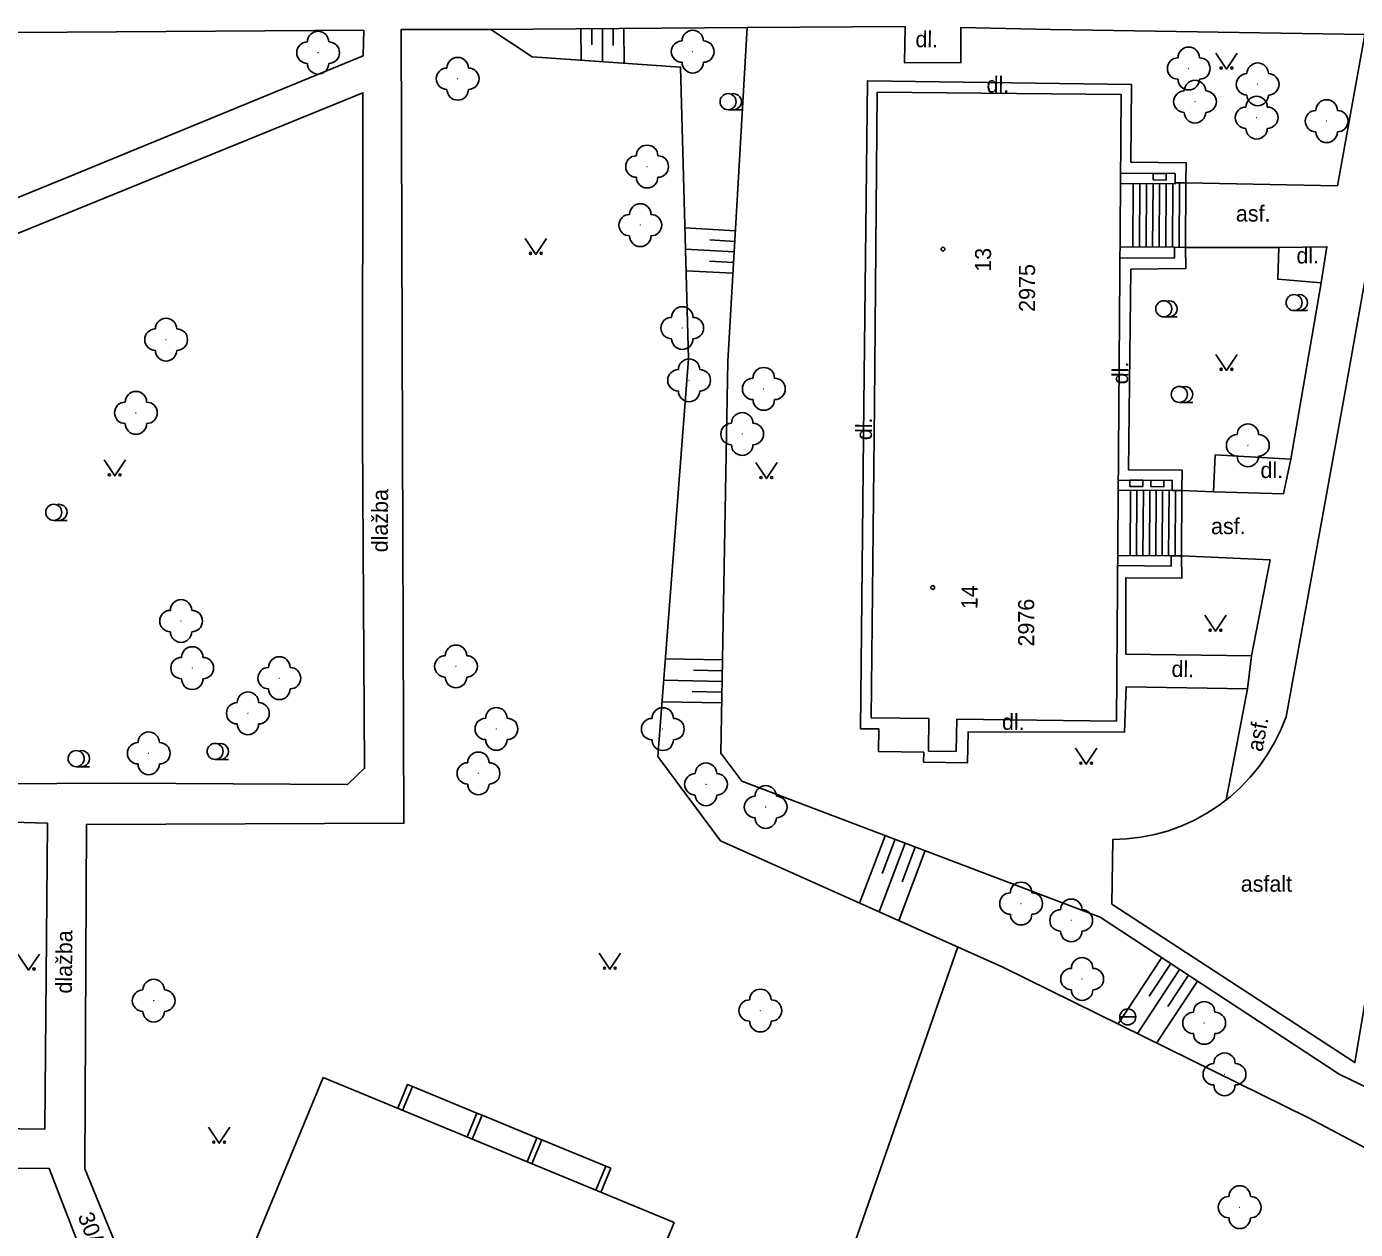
# Model space of a CAD drawing. Extents: x -584400 to -581602, y -1210894 to -1208793.
# Drawn here: x -582480.2 to -582418.1, y -1209940.8 to -1209884.6 of the extents above; entities that cross this region are included whole.
import ezdxf

# ---------------------------------------------------------------- set-up
doc = ezdxf.new("R2010")
doc.units = 0
for name, color, linetype in [('BUDOVY_MĚŘ', 7, 'Continuous'), ('POMOC_POPIS', 7, 'Continuous'), ('ROZHRANÍ_PLOCH', 7, 'Continuous'), ('VÝŠKOPIS', 7, 'Continuous'), ('ZELEŇ', 7, 'Continuous'), ('ZN_BUDOV', 7, 'Continuous'), ('ZN_DOPLŇKOVÉ', 7, 'Continuous'), ('ZN_KULTUR', 7, 'Continuous'), ('Č_POPIS_EVID', 7, 'Continuous')]:
    doc.layers.add(name, color=color, linetype=linetype)

msp = doc.modelspace()

# ---------------------------------------------------------------- linework, layer by layer
at = {"layer": 'BUDOVY_MĚŘ'}
for points in [[(-582440.48, -1209887.69), (-582440.61, -1209902.29)], [(-582429.08, -1209887.81), (-582440.48, -1209887.69)], [(-582429.31, -1209917.09), (-582429.08, -1209887.81)], [(-582427.59, -1209891.49), (-582427.59, -1209891.79)], [(-582426.99, -1209891.5), (-582427.59, -1209891.49)], [(-582426.99, -1209891.5), (-582426.99, -1209891.8)], [(-582426.99, -1209891.8), (-582427.59, -1209891.79)], [(-582440.61, -1209902.29), (-582440.76, -1209916.93)], [(-582428.68, -1209905.83), (-582428.68, -1209906.13)], [(-582428.08, -1209905.83), (-582428.68, -1209905.83)], [(-582428.08, -1209905.83), (-582428.08, -1209906.13)], [(-582427.7, -1209905.83), (-582427.7, -1209906.13)], [(-582427.1, -1209905.84), (-582427.7, -1209905.83)], [(-582427.1, -1209905.84), (-582427.1, -1209906.14)], [(-582428.08, -1209906.13), (-582428.68, -1209906.13)], [(-582427.1, -1209906.14), (-582427.7, -1209906.13)], [(-582440.76, -1209916.93), (-582438.07, -1209916.97)], [(-582438.09, -1209918.49), (-582438.07, -1209916.97)], [(-582436.77, -1209916.99), (-582436.79, -1209918.51)], [(-582436.77, -1209916.99), (-582429.31, -1209917.09)], [(-582436.79, -1209918.51), (-582438.09, -1209918.49)], [(-582466.36, -1209933.74), (-582449.97, -1209940.52), (-582453.87, -1209949.94), (-582470.27, -1209943.18), (-582466.36, -1209933.74)]]:
    msp.add_lwpolyline(points, dxfattribs=at)
at = {"layer": 'ROZHRANÍ_PLOCH'}
for points in [[(-582487.79, -1209884.94), (-582478.32, -1209884.89), (-582464.47, -1209884.8), (-582464.49, -1209885.99), (-582477.95, -1209891.52), (-582496.11, -1209898.92)], [(-582475.85, -1209942.04), (-582477.49, -1209938.01), (-582477.42, -1209921.91), (-582462.59, -1209921.86), (-582462.65, -1209904.04), (-582462.72, -1209884.77), (-582458.53, -1209884.77), (-582446.56, -1209884.67), (-582439.17, -1209884.63), (-582439.21, -1209886.32), (-582436.57, -1209886.31), (-582436.58, -1209884.67), (-582432.38, -1209884.76), (-582417.71, -1209885), (-582418.98, -1209892.07), (-582426.06, -1209891.93), (-582426.05, -1209890.99), (-582428.63, -1209890.97), (-582428.6, -1209887.34), (-582440.94, -1209887.16), (-582441.11, -1209902.31), (-582441.27, -1209917.44), (-582440.41, -1209917.45), (-582440.42, -1209918.51), (-582438.31, -1209918.54), (-582438.32, -1209919), (-582436.26, -1209919.03), (-582436.24, -1209917.59), (-582428.93, -1209917.6), (-582428.86, -1209915.48), (-582423.19, -1209915.58), (-582424.18, -1209920.77)], [(-582415.66, -1209885.04), (-582418.63, -1209901.68), (-582421.38, -1209916.89), (-582421.63, -1209917.5), (-582421.92, -1209918.09), (-582422.26, -1209918.66), (-582422.64, -1209919.2), (-582423.06, -1209919.71), (-582423.51, -1209920.19), (-582424, -1209920.63), (-582424.18, -1209920.77), (-582424.53, -1209921.03), (-582425.08, -1209921.39), (-582425.66, -1209921.71), (-582426.26, -1209921.98), (-582426.88, -1209922.21), (-582427.52, -1209922.38), (-582428.17, -1209922.51), (-582428.82, -1209922.59), (-582429.48, -1209922.62), (-582429.52, -1209925.64), (-582418.17, -1209933.04), (-582417.7, -1209930.28)], [(-582496.62, -1209900.8), (-582477.39, -1209892.97), (-582464.51, -1209887.72), (-582464.52, -1209903.76), (-582464.43, -1209919.29), (-582465.22, -1209920.05), (-582475.91, -1209919.99), (-582484.59, -1209920.04), (-582484.6, -1209914.6), (-582485.27, -1209914.6)], [(-582429.11, -1209891.48), (-582426.57, -1209891.5), (-582426.57, -1209891.98), (-582429.11, -1209891.96)], [(-582428.54, -1209894.93), (-582428.52, -1209891.97)], [(-582428.23, -1209894.93), (-582428.21, -1209891.97)], [(-582427.92, -1209894.93), (-582427.9, -1209891.97)], [(-582427.62, -1209894.93), (-582427.59, -1209891.97)], [(-582427.31, -1209894.93), (-582427.29, -1209891.97)], [(-582427, -1209894.94), (-582426.98, -1209891.98)], [(-582426.69, -1209894.94), (-582426.67, -1209891.98)], [(-582426.6, -1209894.94), (-582426.08, -1209894.95), (-582426.06, -1209891.93), (-582426.57, -1209891.93)], [(-582426.38, -1209894.94), (-582426.36, -1209891.98)], [(-582429.14, -1209894.92), (-582426.6, -1209894.94), (-582426.6, -1209895.45), (-582429.14, -1209895.43)], [(-582424.78, -1209906.37), (-582426.25, -1209906.31), (-582426.24, -1209905.36), (-582428.75, -1209905.34), (-582428.64, -1209895.97), (-582426.07, -1209895.94), (-582426.08, -1209894.95), (-582421.73, -1209894.95), (-582421.77, -1209896.44), (-582419.75, -1209896.61), (-582421.16, -1209904.84), (-582424.69, -1209904.65), (-582424.78, -1209906.37)], [(-582421.73, -1209894.95), (-582419.48, -1209894.92), (-582419.75, -1209896.61)], [(-582424.78, -1209906.37), (-582421.51, -1209906.47), (-582421.16, -1209904.84)], [(-582429.22, -1209905.82), (-582426.7, -1209905.84), (-582426.7, -1209906.31), (-582429.23, -1209906.29)], [(-582428.65, -1209906.3), (-582428.67, -1209909.36)], [(-582428.35, -1209906.3), (-582428.37, -1209909.36)], [(-582428.05, -1209906.3), (-582428.07, -1209909.36)], [(-582427.75, -1209906.3), (-582427.77, -1209909.36)], [(-582427.45, -1209906.3), (-582427.47, -1209909.36)], [(-582427.15, -1209906.31), (-582427.17, -1209909.37)], [(-582426.85, -1209906.31), (-582426.87, -1209909.37)], [(-582426.7, -1209906.31), (-582426.25, -1209906.31), (-582426.27, -1209909.37), (-582426.75, -1209909.37)], [(-582426.55, -1209906.31), (-582426.57, -1209909.37)], [(-582429.25, -1209909.82), (-582426.75, -1209909.84), (-582426.75, -1209909.37), (-582429.25, -1209909.35)], [(-582423, -1209914.04), (-582428.87, -1209913.95), (-582428.87, -1209910.39), (-582426.25, -1209910.4), (-582426.27, -1209909.37), (-582422.13, -1209909.55), (-582423, -1209914.04)], [(-582423, -1209914.04), (-582423.19, -1209915.58)], [(-582479.24, -1209921.86), (-582479.37, -1209936.15), (-582484, -1209936.09), (-582484.04, -1209933.99), (-582480.99, -1209934.06), (-582480.9, -1209921.81), (-582479.24, -1209921.86)], [(-582480.69, -1209957.83), (-582475.89, -1209949.13), (-582475.61, -1209947.19), (-582479.16, -1209938), (-582506.68, -1209937.89), (-582506.72, -1209927.01), (-582507.45, -1209926.2), (-582528.2, -1209925.75), (-582529.35, -1209927.61)], [(-582462.19, -1209934.16), (-582459.18, -1209935.4)], [(-582458.94, -1209935.5), (-582456.38, -1209936.56)], [(-582456.15, -1209936.65), (-582453.16, -1209937.88)]]:
    msp.add_lwpolyline(points, dxfattribs=at)
at = {"layer": 'VÝŠKOPIS'}
for points in [[(-582458.53, -1209884.77), (-582456.6, -1209886.04), (-582449.67, -1209886.53), (-582449.3, -1209900.15), (-582450.73, -1209918.74), (-582447.81, -1209922.68), (-582434.61, -1209928.59), (-582420.34, -1209935.62), (-582401.96, -1209945.35), (-582389.45, -1209947.48)], [(-582454.31, -1209886.2), (-582454.32, -1209884.74)], [(-582453.82, -1209885.48), (-582453.82, -1209884.73)], [(-582453.31, -1209886.27), (-582453.32, -1209884.73)], [(-582452.82, -1209885.51), (-582452.82, -1209884.72)], [(-582452.31, -1209886.34), (-582452.32, -1209884.72)], [(-582391.38, -1209943.01), (-582402.62, -1209941.45), (-582418.91, -1209933.59), (-582430.07, -1209926.24), (-582446.8, -1209919.9), (-582447.79, -1209918.59), (-582447.46, -1209900.26), (-582446.56, -1209884.67)], [(-582449.47, -1209894.03), (-582447.11, -1209894.17)], [(-582448.3, -1209894.6), (-582447.14, -1209894.67)], [(-582449.44, -1209895.03), (-582447.17, -1209895.16)], [(-582449.41, -1209896.04), (-582447.22, -1209896.16)], [(-582448.31, -1209895.6), (-582447.19, -1209895.66)], [(-582450.38, -1209914.18), (-582447.71, -1209914.23)], [(-582450.46, -1209915.18), (-582447.73, -1209915.23)], [(-582449.07, -1209914.7), (-582447.72, -1209914.73)], [(-582449.12, -1209915.7), (-582447.74, -1209915.73)], [(-582450.53, -1209916.18), (-582447.75, -1209916.23)], [(-582441.31, -1209925.59), (-582440.11, -1209922.44)], [(-582440.25, -1209924.2), (-582439.64, -1209922.61)], [(-582440.39, -1209926), (-582439.18, -1209922.79)], [(-582439.48, -1209926.41), (-582438.24, -1209923.14)], [(-582439.32, -1209924.59), (-582438.71, -1209922.97)], [(-582429.23, -1209931.24), (-582427.19, -1209928.14)], [(-582428.33, -1209931.68), (-582426.36, -1209928.69)], [(-582427.78, -1209929.94), (-582426.77, -1209928.41)], [(-582426.91, -1209930.43), (-582425.94, -1209928.96)], [(-582427.43, -1209932.13), (-582425.52, -1209929.24)]]:
    msp.add_lwpolyline(points, dxfattribs=at)
at = {"layer": 'ZELEŇ'}
msp.add_lwpolyline([(-582436.72, -1209927.64), (-582442.95, -1209945.51), (-582431.5, -1209950.17), (-582420.63, -1209954.71), (-582403.11, -1209963.06), (-582400.98, -1209957.39), (-582400.57, -1209953.27)], dxfattribs=at)
for centre in [(-582466.6, -1209885.85), (-582449.1, -1209885.8), (-582425.93, -1209886.59), (-582460.08, -1209887.07), (-582422.71, -1209887.33), (-582425.64, -1209888.14), (-582422.76, -1209888.89), (-582419.49, -1209889.05), (-582451.23, -1209891.17), (-582451.55, -1209893.91), (-582449.59, -1209898.72), (-582473.7, -1209899.26), (-582449.27, -1209901.16), (-582445.78, -1209901.56), (-582475.11, -1209902.68), (-582446.79, -1209903.67), (-582423.17, -1209904.2), (-582473, -1209912.41), (-582472.48, -1209914.61), (-582460.16, -1209914.53), (-582468.41, -1209915.08), (-582469.88, -1209916.72), (-582458.27, -1209917.45), (-582450.5, -1209917.46), (-582474.51, -1209918.59), (-582459.11, -1209919.53), (-582448.48, -1209920.04), (-582445.69, -1209921.1), (-582433.76, -1209925.61), (-582431.42, -1209926.4), (-582430.91, -1209929.14), (-582474.28, -1209930.15), (-582445.94, -1209930.61), (-582425.21, -1209931.19), (-582424.26, -1209933.59), (-582423.55, -1209939.8)]:
    msp.add_circle(centre, 0.0005, dxfattribs=at)
for centre, start, end in [((-582466.6, -1209885.35), 0, 179.99999), ((-582449.1, -1209885.3), 0, 179.99999), ((-582467.1, -1209885.85), 89.99999, 269.99999), ((-582466.1, -1209885.85), 270, 89.99999), ((-582449.6, -1209885.8), 89.99999, 269.99999), ((-582448.6, -1209885.8), 270, 89.99999), ((-582460.08, -1209886.57), 0, 179.99999), ((-582426.43, -1209886.59), 89.99999, 269.99999), ((-582425.93, -1209886.09), 0, 179.99999), ((-582425.43, -1209886.59), 270, 89.99999), ((-582466.6, -1209886.35), 179.99999, 359.99999), ((-582460.58, -1209887.07), 89.99999, 269.99999), ((-582459.58, -1209887.07), 270, 89.99999), ((-582449.1, -1209886.3), 179.99999, 359.99999), ((-582422.71, -1209886.83), 0, 179.99999), ((-582425.93, -1209887.09), 179.99999, 359.99999), ((-582425.64, -1209887.64), 0, 179.99999), ((-582423.21, -1209887.33), 89.99999, 269.99999), ((-582422.21, -1209887.33), 270, 89.99999), ((-582460.08, -1209887.57), 179.99999, 359.99999), ((-582426.14, -1209888.14), 89.99999, 269.99999), ((-582425.14, -1209888.14), 270, 89.99999), ((-582422.76, -1209888.39), 0, 179.99999), ((-582422.71, -1209887.83), 179.99999, 359.99999), ((-582423.26, -1209888.89), 89.99999, 269.99999), ((-582422.26, -1209888.89), 270, 89.99999), ((-582419.99, -1209889.05), 89.99999, 269.99999), ((-582419.49, -1209888.55), 0, 179.99999), ((-582418.99, -1209889.05), 270, 89.99999), ((-582425.64, -1209888.64), 179.99999, 359.99999), ((-582422.76, -1209889.39), 179.99999, 359.99999), ((-582419.49, -1209889.55), 179.99999, 359.99999), ((-582451.23, -1209890.67), 0, 179.99999), ((-582451.73, -1209891.17), 89.99999, 269.99999), ((-582450.73, -1209891.17), 270, 89.99999), ((-582451.23, -1209891.67), 179.99999, 359.99999), ((-582451.55, -1209893.41), 0, 179.99999), ((-582452.05, -1209893.91), 89.99999, 269.99999), ((-582451.05, -1209893.91), 270, 89.99999), ((-582451.55, -1209894.41), 179.99999, 359.99999), ((-582449.59, -1209898.22), 0, 179.99999), ((-582473.7, -1209898.76), 0, 179.99999), ((-582450.09, -1209898.72), 89.99999, 269.99999), ((-582449.09, -1209898.72), 270, 89.99999), ((-582474.2, -1209899.26), 89.99999, 269.99999), ((-582473.2, -1209899.26), 270, 89.99999), ((-582473.7, -1209899.76), 179.99999, 359.99999), ((-582449.59, -1209899.22), 179.99999, 359.99999), ((-582449.27, -1209900.66), 0, 179.99999), ((-582449.77, -1209901.16), 89.99999, 269.99999), ((-582448.77, -1209901.16), 270, 89.99999), ((-582445.78, -1209901.06), 0, 179.99999), ((-582446.28, -1209901.56), 89.99999, 269.99999), ((-582445.28, -1209901.56), 270, 89.99999), ((-582475.61, -1209902.68), 89.99999, 269.99999), ((-582475.11, -1209902.18), 0, 179.99999), ((-582474.61, -1209902.68), 270, 89.99999), ((-582449.27, -1209901.66), 179.99999, 359.99999), ((-582445.78, -1209902.06), 179.99999, 359.99999), ((-582446.79, -1209903.17), 0, 179.99999), ((-582475.11, -1209903.18), 179.99999, 359.99999), ((-582447.29, -1209903.67), 89.99999, 269.99999), ((-582446.29, -1209903.67), 270, 89.99999), ((-582423.17, -1209903.7), 0, 179.99999), ((-582423.67, -1209904.2), 89.99999, 269.99999), ((-582422.67, -1209904.2), 270, 89.99999), ((-582446.79, -1209904.17), 179.99999, 359.99999), ((-582423.17, -1209904.7), 179.99999, 359.99999), ((-582473, -1209911.91), 0, 179.99999), ((-582473.5, -1209912.41), 89.99999, 269.99999), ((-582472.5, -1209912.41), 270, 89.99999), ((-582473, -1209912.91), 179.99999, 359.99999), ((-582472.48, -1209914.11), 0, 179.99999), ((-582460.66, -1209914.53), 89.99999, 269.99999), ((-582460.16, -1209914.03), 0, 179.99999), ((-582459.66, -1209914.53), 270, 89.99999), ((-582472.98, -1209914.61), 89.99999, 269.99999), ((-582471.98, -1209914.61), 270, 89.99999), ((-582468.91, -1209915.08), 89.99999, 269.99999), ((-582468.41, -1209914.58), 0, 179.99999), ((-582467.91, -1209915.08), 270, 89.99999), ((-582472.48, -1209915.11), 179.99999, 359.99999), ((-582460.16, -1209915.03), 179.99999, 359.99999), ((-582469.88, -1209916.22), 0, 179.99999), ((-582468.41, -1209915.58), 179.99999, 359.99999), ((-582470.38, -1209916.72), 89.99999, 269.99999), ((-582469.38, -1209916.72), 270, 89.99999), ((-582458.27, -1209916.95), 0, 179.99999), ((-582450.5, -1209916.96), 0, 179.99999), ((-582458.77, -1209917.45), 89.99999, 269.99999), ((-582457.77, -1209917.45), 270, 89.99999), ((-582451, -1209917.46), 89.99999, 269.99999), ((-582450, -1209917.46), 270, 89.99999), ((-582474.51, -1209918.09), 0, 179.99999), ((-582469.88, -1209917.22), 179.99999, 359.99999), ((-582475.01, -1209918.59), 89.99999, 269.99999), ((-582474.01, -1209918.59), 270, 89.99999), ((-582458.27, -1209917.95), 179.99999, 359.99999), ((-582450.5, -1209917.96), 179.99999, 359.99999), ((-582459.61, -1209919.53), 89.99999, 269.99999), ((-582459.11, -1209919.03), 0, 179.99999), ((-582458.61, -1209919.53), 270, 89.99999), ((-582474.51, -1209919.09), 179.99999, 359.99999), ((-582448.98, -1209920.04), 89.99999, 269.99999), ((-582448.48, -1209919.54), 0, 179.99999), ((-582447.98, -1209920.04), 270, 89.99999), ((-582459.11, -1209920.03), 179.99999, 359.99999), ((-582445.69, -1209920.6), 0, 179.99999), ((-582448.48, -1209920.54), 179.99999, 359.99999), ((-582446.19, -1209921.1), 89.99999, 269.99999), ((-582445.19, -1209921.1), 270, 89.99999), ((-582445.69, -1209921.6), 179.99999, 359.99999), ((-582433.76, -1209925.11), 0, 179.99999), ((-582434.26, -1209925.61), 89.99999, 269.99999), ((-582433.26, -1209925.61), 270, 89.99999), ((-582431.42, -1209925.9), 0, 179.99999), ((-582433.76, -1209926.11), 179.99999, 359.99999), ((-582431.92, -1209926.4), 89.99999, 269.99999), ((-582430.92, -1209926.4), 270, 89.99999), ((-582431.42, -1209926.9), 179.99999, 359.99999), ((-582430.91, -1209928.64), 0, 179.99999), ((-582431.41, -1209929.14), 89.99999, 269.99999), ((-582430.41, -1209929.14), 270, 89.99999), ((-582474.28, -1209929.65), 0, 179.99999), ((-582474.78, -1209930.15), 89.99999, 269.99999), ((-582473.78, -1209930.15), 270, 89.99999), ((-582446.44, -1209930.61), 89.99999, 269.99999), ((-582445.94, -1209930.11), 0, 179.99999), ((-582445.44, -1209930.61), 270, 89.99999), ((-582430.91, -1209929.64), 179.99999, 359.99999), ((-582425.21, -1209930.69), 0, 179.99999), ((-582474.28, -1209930.65), 179.99999, 359.99999), ((-582425.71, -1209931.19), 89.99999, 269.99999), ((-582424.71, -1209931.19), 270, 89.99999), ((-582445.94, -1209931.11), 179.99999, 359.99999), ((-582425.21, -1209931.69), 179.99999, 359.99999), ((-582424.26, -1209933.09), 0, 179.99999), ((-582424.76, -1209933.59), 89.99999, 269.99999), ((-582423.76, -1209933.59), 270, 89.99999), ((-582424.26, -1209934.09), 179.99999, 359.99999), ((-582423.55, -1209939.3), 0, 179.99999), ((-582424.05, -1209939.8), 89.99999, 269.99999), ((-582423.05, -1209939.8), 270, 89.99999), ((-582423.55, -1209940.3), 179.99999, 359.99999)]:
    msp.add_arc(centre, 0.5, start, end, dxfattribs=at)
at = {"layer": 'ZN_BUDOV'}
for centre in [(-582437.41, -1209895.03), (-582437.89, -1209910.84)]:
    msp.add_circle(centre, 0.0875, dxfattribs=at)
at = {"layer": 'ZN_DOPLŇKOVÉ'}
msp.add_line((-582429.155, -1209930.91), (-582428.405, -1209930.91), dxfattribs=at)
for points in [[(-582462.88, -1209935.18), (-582462.43, -1209934.06), (-582462.19, -1209934.16)], [(-582462.65, -1209935.28), (-582462.19, -1209934.16)], [(-582459.64, -1209936.52), (-582459.18, -1209935.4), (-582458.94, -1209935.5)], [(-582459.41, -1209936.62), (-582458.94, -1209935.5)], [(-582456.84, -1209937.68), (-582456.38, -1209936.56), (-582456.15, -1209936.65)], [(-582456.61, -1209937.77), (-582456.15, -1209936.65)], [(-582453.63, -1209939.01), (-582453.16, -1209937.88), (-582452.93, -1209937.98)], [(-582453.4, -1209939.11), (-582452.93, -1209937.98)]]:
    msp.add_lwpolyline(points, dxfattribs=at)
msp.add_circle((-582428.78, -1209930.91), 0.375, dxfattribs=at)
at = {"layer": 'ZN_KULTUR'}
for p, q in [((-582447.45, -1209888.515), (-582446.825, -1209888.515)), ((-582421.01, -1209897.905), (-582420.385, -1209897.905)), ((-582427.1, -1209898.195), (-582426.475, -1209898.195)), ((-582426.37, -1209902.195), (-582425.745, -1209902.195)), ((-582478.95, -1209907.705), (-582478.325, -1209907.705)), ((-582471.41, -1209918.875), (-582470.785, -1209918.875)), ((-582477.9, -1209919.215), (-582477.275, -1209919.215))]:
    msp.add_line(p, q, dxfattribs=at)
for points in [[(-582424.67, -1209885.87), (-582424.17, -1209886.62), (-582423.67, -1209885.87)], [(-582456.93, -1209894.53), (-582456.43, -1209895.28), (-582455.93, -1209894.53)], [(-582424.67, -1209899.95), (-582424.17, -1209900.7), (-582423.67, -1209899.95)], [(-582476.6, -1209904.88), (-582476.1, -1209905.63), (-582475.6, -1209904.88)], [(-582446.16, -1209905), (-582445.66, -1209905.75), (-582445.16, -1209905)], [(-582425.18, -1209912.14), (-582424.68, -1209912.89), (-582424.18, -1209912.14)], [(-582431.22, -1209918.35), (-582430.72, -1209919.1), (-582430.22, -1209918.35)], [(-582480.62, -1209927.97), (-582480.12, -1209928.72), (-582479.62, -1209927.97)], [(-582453.47, -1209927.93), (-582452.97, -1209928.68), (-582452.47, -1209927.93)], [(-582471.72, -1209936.06), (-582471.22, -1209936.81), (-582470.72, -1209936.06)]]:
    msp.add_lwpolyline(points, dxfattribs=at)
for centre, radius in [((-582424.42, -1209886.57), 0.05), ((-582423.92, -1209886.57), 0.05), ((-582447.45, -1209888.14), 0.375), ((-582456.68, -1209895.23), 0.05), ((-582456.18, -1209895.23), 0.05), ((-582421.01, -1209897.53), 0.375), ((-582427.1, -1209897.82), 0.375), ((-582424.42, -1209900.65), 0.05), ((-582423.92, -1209900.65), 0.05), ((-582426.37, -1209901.82), 0.375), ((-582476.35, -1209905.58), 0.05), ((-582475.85, -1209905.58), 0.05), ((-582445.91, -1209905.7), 0.05), ((-582445.41, -1209905.7), 0.05), ((-582478.95, -1209907.33), 0.375), ((-582424.93, -1209912.84), 0.05), ((-582424.43, -1209912.84), 0.05), ((-582471.41, -1209918.5), 0.375), ((-582477.9, -1209918.84), 0.375), ((-582430.97, -1209919.05), 0.05), ((-582430.47, -1209919.05), 0.05), ((-582479.87, -1209928.67), 0.05), ((-582453.22, -1209928.63), 0.05), ((-582452.72, -1209928.63), 0.05), ((-582471.47, -1209936.76), 0.05), ((-582470.97, -1209936.76), 0.05)]:
    msp.add_circle(centre, radius, dxfattribs=at)
for centre in [(-582447.2, -1209888.14), (-582420.76, -1209897.53), (-582426.85, -1209897.82), (-582426.12, -1209901.82), (-582478.7, -1209907.33), (-582471.16, -1209918.5), (-582477.65, -1209918.84)]:
    msp.add_arc(centre, 0.375, 249.49437, 109.04743, dxfattribs=at)

# ---------------------------------------------------------------- texts
at = {"layer": 'POMOC_POPIS'}
for s, rotation, p in [('dl.', 359.19939, (-582438.7, -1209885.59)), ('dl.', 359.19939, (-582435.38, -1209887.71)), ('dl.', 89.45137, (-582428.76, -1209901.35)), ('dl.', 89.45137, (-582440.73, -1209903.96)), ('dlažba', 89.54792, (-582463.35, -1209909.2)), ('dl.', 359.19939, (-582426.74, -1209915.02)), ('dl.', 359.19939, (-582434.66, -1209917.49)), ('asf.', 79.77618, (-582422.49, -1209918.55)), ('dlažba', 89.54792, (-582478.1, -1209929.82)), ('30/30 dl.', 291.13733, (-582477.84, -1209940.21))]:
    msp.add_text(s, height=0.75, rotation=rotation, dxfattribs=at).set_placement(p)
for s, p in [('asf.', (-582423.73, -1209893.74)), ('dl.', (-582420.9, -1209895.7)), ('dl.', (-582422.58, -1209905.73)), ('asf.', (-582424.89, -1209908.35)), ('asfalt', (-582423.5, -1209925.06))]:
    msp.add_text(s, height=0.75, dxfattribs=at).set_placement(p)
at = {"layer": 'Č_POPIS_EVID'}
for s, rotation, p in [('13', 89.49205, (-582435.17, -1209896.09)), ('2975', 89.99998, (-582433.11, -1209897.96)), ('14', 89.49205, (-582435.8, -1209911.86)), ('2976', 89.99998, (-582433.15, -1209913.6))]:
    msp.add_text(s, height=0.75, rotation=rotation, dxfattribs=at).set_placement(p)

doc.saveas('drawing.dxf')
